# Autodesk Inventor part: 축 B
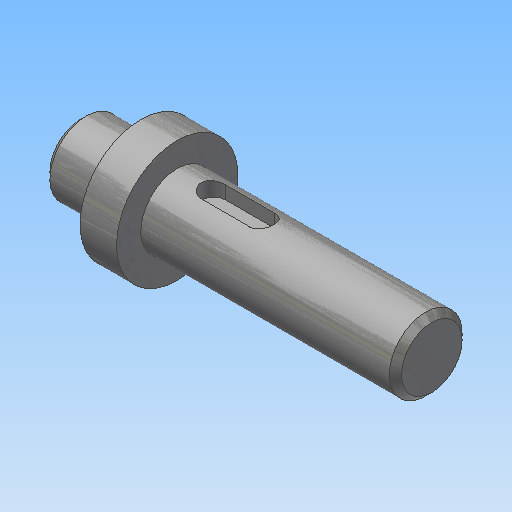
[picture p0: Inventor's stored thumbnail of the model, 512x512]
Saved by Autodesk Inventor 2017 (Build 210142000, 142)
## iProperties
Created: 2020-04
Part Number: 축 B
Material: 강철, 연강
Document SubType Name: Modeling
Designer: mduedu
Density: 7.86 g/cm^3
Mass: 57.2004 g
Surface Area: 29.0657 cm^2
Volume: 7.2774 cm^3
Appearance: 강철
Author: mduedu
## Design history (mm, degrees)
revolve "회전1" stored, may be unused: angle "d11" = 90 deg
sketch "스케치3"
  geometry: L1 (0, -6)-(0, 6) reference; L2 (0, 6)-(10, 6) reference; L3 (10, 6)-(10, 10) reference; L4 (10, 10)-(16, 10) reference; L5 (16, 10)-(16, 6) reference; L6 (16, 6)-(58, 6) reference; L7 (58, 6)-(58, -6) reference; L8 (58, -6)-(16, -6) reference; L9 (16, -6)-(16, -10) reference; L10 (16, -10)-(10, -10) reference; L11 (10, -10)-(10, -6) reference; L12 (10, -6)-(0, -6) reference; L13 (20, 6)-(32, 6); L14 (32, 6)-(32, 3.5); L15 (32, 3.5)-(20, 3.5); L16 (20, 3.5)-(20, 6); 1 further point
  constraints: 8 end point, 2 parallel, 1 horizontal, 1 perpendicular, 1 point on line
  dimensions: "d17" = 12 distance of L14.end L15.end; "d18" = 2.5 distance of L13.end L14.end; "d19" = 4 distance from line of L16 L4.end
extrude "돌출2" cut sketch "스케치3" stored distance "d20" = 4; taper "d21" = 0 deg
fillet "모깎기2" dims "d22" = 2
chamfer "모따기1" distance "d23" = 1; stored, may be unused: second distance "d24" = 2, angle "d25" = 45 deg
chamfer "모따기2" distance "d26" = 1; stored, may be unused: second distance "d27" = 2, angle "d28" = 45 deg
fillet "모깎기3" dims "d29" = 0.3
node "솔리드1"
sketch "스케치1"
  geometry: L1 (0, 0)-(10, 0); L2 (10, 0)-(10, 6); L3 (10, 6)-(0, 6); L4 (0, 6)-(0, 0); L5 (10, 0)-(16, 0); L6 (16, 0)-(16, 10); L7 (16, 10)-(10, 10); L8 (10, 10)-(10, 0); L9 (16, 0)-(58, 0); L10 (58, 0)-(58, 6); L11 (58, 6)-(16, 6); L12 (16, 6)-(16, 0); L13 (58, 0)-(58, 0); L14 (58, 5)-(58, 0)
  constraints: 28 end point, 6 parallel, 4 horizontal, 3 perpendicular
  dimensions: "d2" = 10 distance of L2.end L3.end; "d3" = 6 distance of L6.end L7.end; "d7" = 12 diameter of L11 L9; "d8" = 12 diameter of L3 L1; "d9" = 20 diameter of L7 L5; "d36" = 58 distance between parallel lines of L10 L4
node "절단 모서리 투영2"
